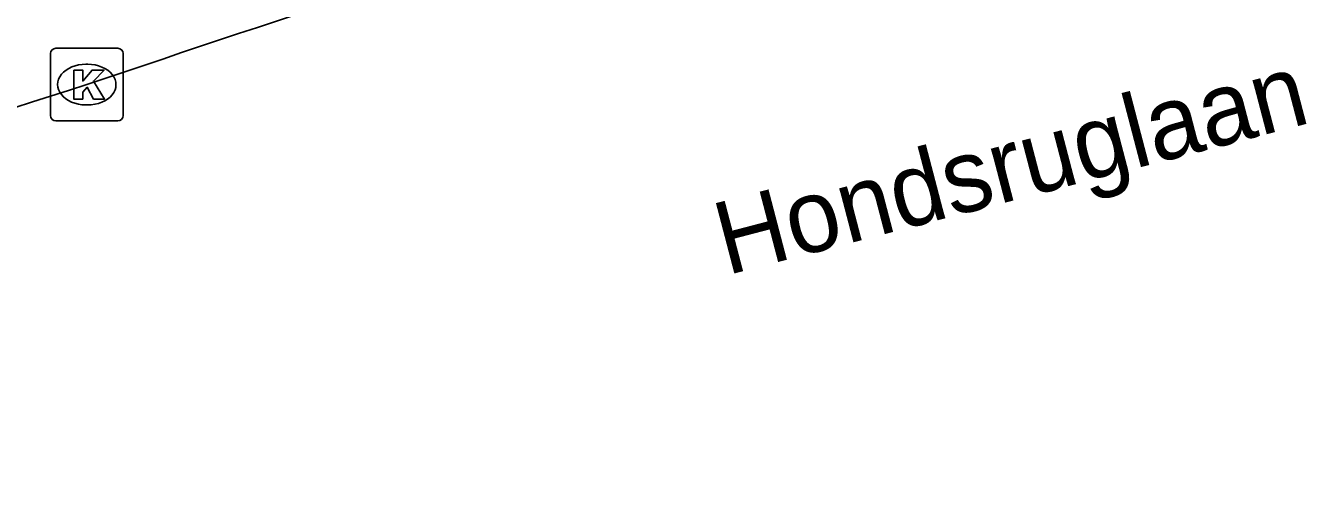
# Model space of a CAD drawing. Extents: x 159628 to 160723, y 388176 to 389416.
# Drawn here: x 159987.78 to 160005.43, y 388261 to 388267.3 of the extents above; entities that cross this region are included whole.
import ezdxf

# ---------------------------------------------------------------- set-up
doc = ezdxf.new("R2010")
doc.units = 0
for name, color, linetype in [('IMGEO_Kolk', 7, 'Continuous'), ('IMGEO_Openbare_ruimte_label', 7, 'Continuous'), ('IMGEO_Rijbaan_regionaal_gesloten', 7, 'Continuous')]:
    doc.layers.add(name, color=color, linetype=linetype)

msp = doc.modelspace()

# ---------------------------------------------------------------- linework, layer by layer
at = {"layer": 'IMGEO_Kolk'}
for p, q in [((159988.193, 388266.989), (159989.045, 388266.989)), ((159988.118, 388266.063), (159988.118, 388266.915)), ((159988.606, 388266.769), (159988.631, 388266.769)), ((159989.119, 388266.915), (159989.119, 388266.063)), ((159988.629, 388266.209), (159988.604, 388266.209)), ((159989.045, 388265.989), (159988.193, 388265.989))]:
    msp.add_line(p, q, dxfattribs=at)
for points in [[(159988.193, 388266.989), (159989.045, 388266.989)], [(159988.118, 388266.063), (159988.118, 388266.915)], [(159989.119, 388266.915), (159989.119, 388266.063)], [(159988.439, 388266.689), (159988.562, 388266.689), (159988.562, 388266.538), (159988.692, 388266.689), (159988.856, 388266.689), (159988.71, 388266.538), (159988.863, 388266.289), (159988.711, 388266.289), (159988.626, 388266.453), (159988.562, 388266.386), (159988.562, 388266.289), (159988.439, 388266.289), (159988.439, 388266.689)], [(159989.045, 388265.989), (159988.193, 388265.989)]]:
    msp.add_lwpolyline(points, dxfattribs=at)
for centre, start, end in [((159988.195, 388266.913), 91.552, 178.448), ((159988.195, 388266.913), 91.552, 178.448), ((159989.043, 388266.913), 1.552, 88.448), ((159989.043, 388266.913), 1.552, 88.448), ((159988.195, 388266.065), 181.552, 268.448), ((159988.195, 388266.065), 181.552, 268.448), ((159989.043, 388266.065), 271.552, 358.448), ((159989.043, 388266.065), 271.552, 358.448)]:
    msp.add_arc(centre, 0.0765, start, end, dxfattribs=at)
for centre, major_axis, ratio, start_param, end_param in [((159988.605, 388266.489), (-0.387, 0.002), 0.722429, 4.712389, 7.853982), ((159988.63, 388266.489), (-0.39, 0.002), 0.717154, 1.570796, 4.712389)]:
    msp.add_ellipse(centre, major_axis=major_axis, ratio=ratio, start_param=start_param, end_param=end_param, dxfattribs=at)
at = {"layer": 'IMGEO_Rijbaan_regionaal_gesloten'}
for centre, radius, start, end in [((160105.803, 387921.072), 364.753, 105.97341, 108.73968), ((160088.816, 387951.623), 330.424, 107.65221, 110.55838)]:
    msp.add_arc(centre, radius, start, end, dxfattribs=at)

# ---------------------------------------------------------------- texts
at = {"layer": 'IMGEO_Openbare_ruimte_label'}
msp.add_text('Hondsruglaan', height=1, rotation=14.6619, dxfattribs=at).set_placement((159997.415, 388263.863))

doc.saveas('drawing.dxf')
